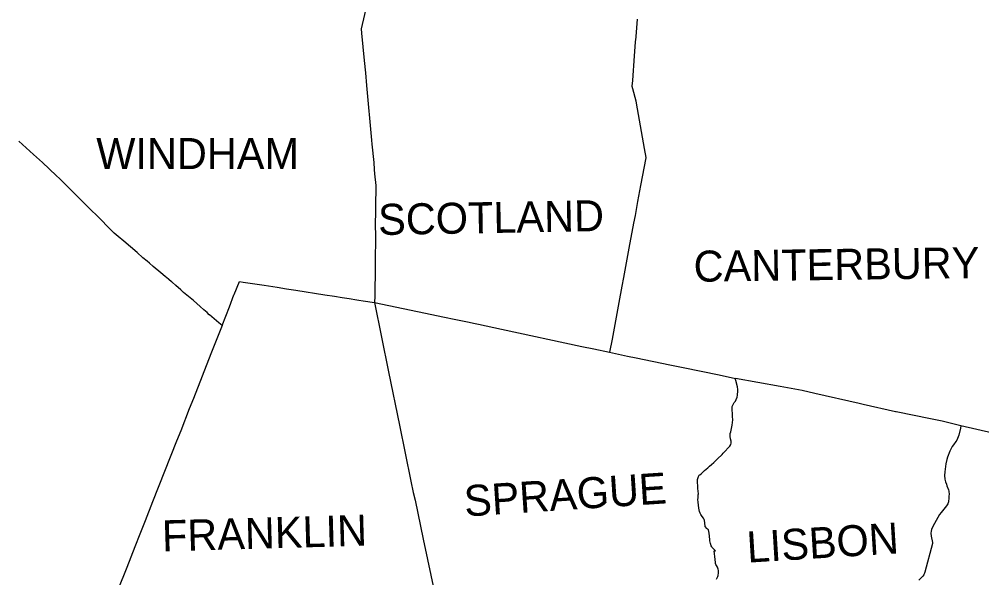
# Model space of a CAD drawing. Extents: x 0 to 2603, y -226 to 830.
# Drawn here: x 287.25 to 329.14, y 603.47 to 627.77 of the extents above; entities that cross this region are included whole.
import ezdxf

# ---------------------------------------------------------------- set-up
doc = ezdxf.new("R2010")
doc.units = 0
doc.layers.add('CT_TSH_Map_Town_Limits', color=7, linetype='Continuous')
doc.layers.add('CT_TSH_Map_Town_Text', color=7, linetype='Continuous')

msp = doc.modelspace()

# ---------------------------------------------------------------- linework, layer by layer
at = {"layer": 'CT_TSH_Map_Town_Limits'}
for points in [[(303.982, 635.202), (303.78, 634.351), (303.709, 634.047), (302.947, 630.84), (302.835, 630.342), (302.427, 628.597), (302.126, 627.353), (302.15, 627.163), (302.267, 625.97), (302.315, 625.433), (302.37, 624.885), (302.587, 622.508), (302.601, 622.333), (302.677, 621.533), (302.697, 621.229), (302.717, 621.047), (302.764, 620.53), (302.748, 618.644), (302.75, 618.522), (302.737, 617.011), (302.724, 615.727), (302.713, 615.444)], [(314.147, 627.771), (314.087, 627.026), (314.082, 626.996), (314.063, 626.782), (314.051, 626.571), (314.018, 626.182), (313.939, 625.11), (313.917, 624.865), (313.936, 624.757), (314.091, 624.222), (314.106, 624.122), (314.454, 622.142), (314.526, 621.753), (314.52, 621.74), (314.298, 620.539), (314.163, 619.835), (314.052, 619.233), (313.987, 618.899), (313.787, 617.804), (313.548, 616.538), (313.482, 616.159), (313.347, 615.442), (313.052, 613.848), (312.945, 613.285)], [(296.081, 614.448), (295.932, 614.565), (295.528, 614.902), (295.517, 614.908), (295.429, 615.006), (295.288, 615.122), (295.13, 615.269), (294.831, 615.529), (294.397, 615.882), (294.279, 615.991), (294.059, 616.179), (293.899, 616.335), (293.878, 616.345), (293.758, 616.442), (293.749, 616.455), (293.604, 616.574), (293.413, 616.742), (293.082, 617.018), (292.912, 617.153), (292.823, 617.238), (292.634, 617.394), (292.382, 617.621), (291.798, 618.113), (291.559, 618.32), (291.383, 618.465), (291.289, 618.552), (290.621, 619.23), (290.383, 619.456), (290.064, 619.783), (289.77, 620.077), (289.757, 620.086), (289.353, 620.494), (289.227, 620.613), (289.02, 620.822), (288.856, 620.976), (288.257, 621.534), (287.865, 621.884), (287.23, 622.465)], [(296.081, 614.448), (296.394, 615.257), (296.588, 615.778), (296.605, 615.798), (296.831, 616.358), (296.997, 616.337), (297.909, 616.193), (298.482, 616.107), (298.878, 616.04), (299.289, 615.981), (300.557, 615.779), (300.973, 615.718), (301.306, 615.659), (301.614, 615.616), (301.945, 615.563), (302.026, 615.547), (302.221, 615.516), (302.713, 615.444)], [(302.713, 615.444), (304.591, 615.052), (305.761, 614.807), (305.909, 614.778), (306.038, 614.752), (306.392, 614.677), (306.834, 614.587), (307.027, 614.553), (307.239, 614.506), (308.244, 614.288), (311.743, 613.537), (312.263, 613.426), (312.945, 613.285)], [(302.713, 615.444), (303.32, 612.429), (303.8, 610.105), (304.295, 607.665), (304.396, 607.18), (304.478, 606.851), (304.826, 605.141), (305.685, 601.128)], [(296.081, 614.448), (295.587, 613.21), (294.832, 611.275), (294.647, 610.824), (294.281, 609.854), (294.094, 609.418), (293.047, 606.773), (292.726, 605.95), (292.497, 605.371), (292.283, 604.813), (291.932, 603.919), (290.701, 600.858), (290.464, 600.245), (290.142, 599.44), (289.803, 598.588)], [(312.945, 613.285), (313.725, 613.113), (314.097, 613.035), (315.571, 612.733), (316.143, 612.62), (317.708, 612.293), (318.421, 612.141)], [(318.221, 609.819), (318.279, 610.108), (318.303, 610.345), (318.302, 610.49), (318.298, 610.655), (318.286, 610.712), (318.281, 610.808), (318.276, 610.847), (318.278, 610.883), (318.288, 610.914), (318.292, 610.942), (318.304, 610.976), (318.37, 611.088), (318.419, 611.148), (318.457, 611.223), (318.493, 611.326), (318.512, 611.408), (318.532, 611.602), (318.532, 611.657), (318.513, 611.775), (318.437, 612.056), (318.42, 612.096), (318.421, 612.141)], [(328.229, 610.085), (327.422, 610.276), (326.921, 610.384), (325.422, 610.683), (325.392, 610.69), (323.976, 611.004), (323.808, 611.055), (321.879, 611.492), (321.321, 611.612), (320.366, 611.794), (318.421, 612.141)], [(328.229, 610.085), (328.222, 609.981), (328.149, 609.671), (328.094, 609.525), (328.06, 609.458), (328.022, 609.402), (327.909, 609.256), (327.852, 609.174), (327.759, 608.983), (327.656, 608.715), (327.628, 608.612), (327.588, 608.423), (327.535, 608.082), (327.521, 607.92), (327.541, 607.753), (327.573, 607.636), (327.607, 607.539), (327.623, 607.465), (327.694, 607.297), (327.711, 607.24), (327.726, 607.093), (327.712, 607.034), (327.709, 606.942), (327.697, 606.775), (327.669, 606.687), (327.616, 606.591), (327.377, 606.313), (327.312, 606.227), (327.016, 605.697), (326.962, 605.567), (326.945, 605.502), (326.934, 605.405), (326.945, 605.272), (326.999, 604.998), (327.002, 604.952), (326.665, 603.71), (326.621, 603.588), (326.581, 603.54), (326.405, 603.361)], [(331.819, 609.272), (331.192, 609.393), (330.826, 609.484), (328.229, 610.085)], [(317.599, 603.401), (317.657, 603.526), (317.671, 603.57), (317.686, 603.677), (317.691, 603.727), (317.689, 603.781), (317.677, 603.835), (317.643, 603.924), (317.596, 603.997), (317.57, 604.049), (317.556, 604.089), (317.55, 604.129), (317.542, 604.264), (317.499, 604.641), (317.553, 604.64), (317.476, 604.709), (317.416, 604.78), (317.392, 604.818), (317.371, 604.859), (317.338, 604.954), (317.314, 605.073), (317.303, 605.131), (317.282, 605.405), (317.271, 605.488), (317.25, 605.547), (317.209, 605.587), (317.18, 605.609), (317.112, 605.702), (317.086, 605.853), (317.075, 605.959), (317.067, 606.007), (317.029, 606.059), (316.968, 606.128), (316.915, 606.226), (316.886, 606.285), (316.864, 606.345), (316.829, 606.498), (316.797, 606.754), (316.786, 606.88), (316.797, 606.952), (316.808, 607.015), (316.808, 607.077), (316.812, 607.127), (316.791, 607.35), (316.77, 607.732), (316.778, 607.747), (316.81, 607.872), (316.824, 607.903), (316.846, 607.927), (316.877, 607.949), (316.926, 607.997), (316.976, 608.033), (317.079, 608.132), (317.217, 608.247), (317.291, 608.321), (317.384, 608.399), (317.477, 608.49), (317.647, 608.636), (317.844, 608.837), (317.885, 608.885), (317.91, 608.911), (318.177, 609.188), (318.229, 609.265), (318.244, 609.319), (318.238, 609.416), (318.209, 609.508), (318.188, 609.621), (318.187, 609.676), (318.193, 609.743), (318.221, 609.819)]]:
    msp.add_lwpolyline(points, dxfattribs=at)

# ---------------------------------------------------------------- texts
at = {"layer": 'CT_TSH_Map_Town_Text'}
msp.add_text('WINDHAM', height=1.35, dxfattribs=at).set_placement((290.602, 621.251))
for s, rotation, p in [('SCOTLAND', 1.0252, (302.883, 618.38)), ('CANTERBURY', 0.7545, (316.612, 616.345)), ('SPRAGUE', 3.7598, (306.654, 606.129)), ('FRANKLIN', 1.6206, (293.479, 604.614)), ('LISBON', 3.5283, (318.956, 604.124))]:
    msp.add_text(s, height=1.35, rotation=rotation, dxfattribs=at).set_placement(p)

doc.saveas('drawing.dxf')
